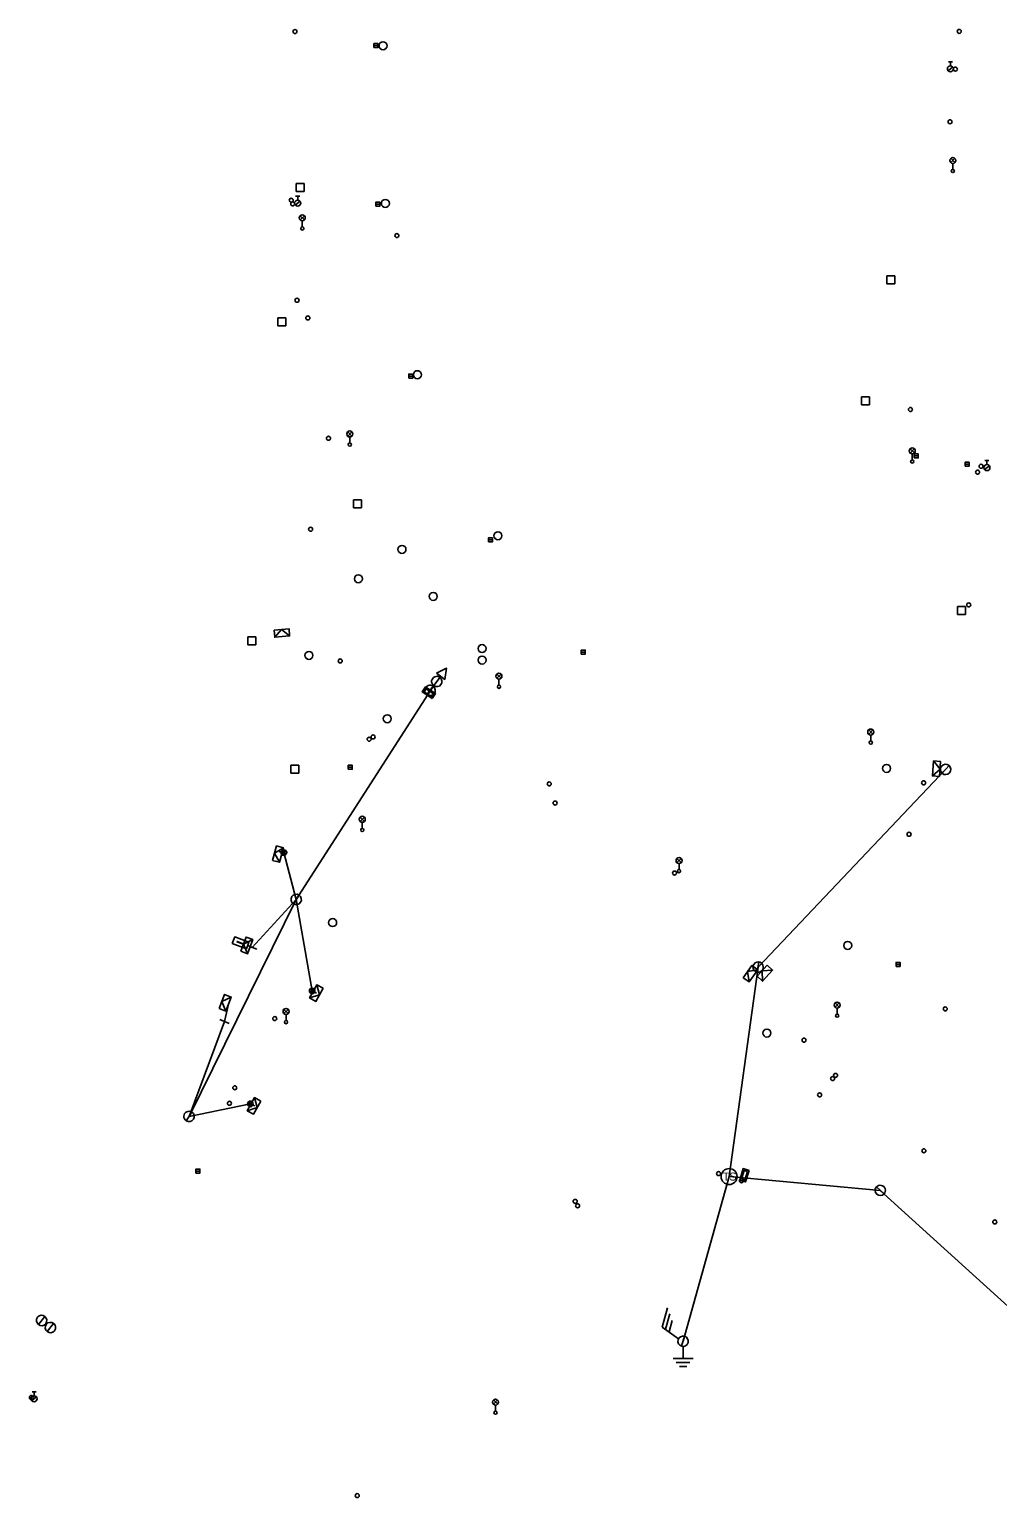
# Model space of a CAD drawing. Extents: x -544660 to -541587, y -1198996 to -1195866.
# Drawn here: x -543889.9 to -543769, y -1197450.3 to -1197266.9 of the extents above; entities that cross this region are included whole.
import ezdxf

# ---------------------------------------------------------------- set-up
doc = ezdxf.new("R2010")
doc.units = 0
doc.layers.add('CIZÍ_NADZEM', color=7, linetype='Continuous')
doc.layers.add('ELE_EON', color=7, linetype='Continuous')

msp = doc.modelspace()

# ---------------------------------------------------------------- linework, layer by layer
at = {"layer": 'CIZÍ_NADZEM'}
for p, q in [((-543846.85, -1197268.9), (-543846.35, -1197268.9)), ((-543775.11, -1197270.94), (-543774.61, -1197270.94)), ((-543774.86, -1197271.44), (-543774.86, -1197270.94)), ((-543775.15, -1197272.04), (-543774.56, -1197271.58)), ((-543774.81, -1197283.52), (-543774.29, -1197282.99)), ((-543774.28, -1197283.52), (-543774.81, -1197282.99)), ((-543774.55, -1197283.63), (-543774.55, -1197284.38)), ((-543855.55, -1197286.13), (-543856.55, -1197286.13)), ((-543856.55, -1197286.13), (-543856.55, -1197287.13)), ((-543855.55, -1197287.13), (-543855.55, -1197286.13)), ((-543856.63, -1197287.72), (-543856.13, -1197287.72)), ((-543856.55, -1197287.13), (-543855.55, -1197287.13)), ((-543856.38, -1197288.22), (-543856.38, -1197287.72)), ((-543856.67, -1197288.82), (-543856.08, -1197288.36)), ((-543846.62, -1197288.72), (-543846.12, -1197288.72)), ((-543856.06, -1197290.69), (-543855.54, -1197290.16)), ((-543855.53, -1197290.69), (-543856.06, -1197290.16)), ((-543855.8, -1197290.8), (-543855.8, -1197291.55)), ((-543781.78, -1197297.67), (-543782.78, -1197297.67)), ((-543782.78, -1197297.67), (-543782.78, -1197298.67)), ((-543782.78, -1197298.67), (-543781.78, -1197298.67)), ((-543781.78, -1197298.67), (-543781.78, -1197297.67)), ((-543857.86, -1197302.91), (-543858.86, -1197302.91)), ((-543858.86, -1197302.91), (-543858.86, -1197303.91)), ((-543858.86, -1197303.91), (-543857.86, -1197303.91)), ((-543857.86, -1197303.91), (-543857.86, -1197302.91)), ((-543842.5, -1197310.2), (-543842, -1197310.2)), ((-543784.97, -1197312.78), (-543785.97, -1197312.78)), ((-543785.97, -1197312.78), (-543785.97, -1197313.78)), ((-543784.97, -1197313.78), (-543784.97, -1197312.78)), ((-543785.97, -1197313.78), (-543784.97, -1197313.78)), ((-543850.13, -1197317.69), (-543849.61, -1197317.16)), ((-543849.6, -1197317.69), (-543850.13, -1197317.16)), ((-543849.87, -1197317.8), (-543849.87, -1197318.55)), ((-543779.88, -1197319.81), (-543779.36, -1197319.28)), ((-543779.35, -1197319.8), (-543779.88, -1197319.28)), ((-543779.62, -1197319.92), (-543779.62, -1197320.67)), ((-543779.36, -1197320.16), (-543778.86, -1197320.16)), ((-543770.54, -1197320.76), (-543770.04, -1197320.76)), ((-543770.29, -1197321.26), (-543770.29, -1197320.76)), ((-543773.03, -1197321.21), (-543772.53, -1197321.21)), ((-543770.58, -1197321.86), (-543769.99, -1197321.4)), ((-543848.39, -1197325.67), (-543849.39, -1197325.67)), ((-543849.39, -1197325.67), (-543849.39, -1197326.67)), ((-543848.39, -1197326.67), (-543848.39, -1197325.67)), ((-543849.39, -1197326.67), (-543848.39, -1197326.67)), ((-543832.56, -1197330.67), (-543832.06, -1197330.67)), ((-543772.97, -1197339), (-543773.97, -1197339)), ((-543773.97, -1197339), (-543773.97, -1197340)), ((-543772.97, -1197340), (-543772.97, -1197339)), ((-543773.97, -1197340), (-543772.97, -1197340)), ((-543861.59, -1197342.78), (-543862.59, -1197342.78)), ((-543862.59, -1197342.78), (-543862.59, -1197343.78)), ((-543861.59, -1197343.78), (-543861.59, -1197342.78)), ((-543862.59, -1197343.78), (-543861.59, -1197343.78)), ((-543820.97, -1197344.67), (-543820.47, -1197344.67)), ((-543831.5, -1197347.95), (-543830.98, -1197347.42)), ((-543830.97, -1197347.95), (-543831.5, -1197347.42)), ((-543831.24, -1197348.06), (-543831.24, -1197348.81)), ((-543785.06, -1197354.92), (-543784.54, -1197354.39)), ((-543784.53, -1197354.92), (-543785.06, -1197354.39)), ((-543784.8, -1197355.03), (-543784.8, -1197355.78)), ((-543857.22, -1197358.79), (-543857.22, -1197359.79)), ((-543856.22, -1197358.79), (-543857.22, -1197358.79)), ((-543856.22, -1197359.79), (-543856.22, -1197358.79)), ((-543850.07, -1197359.06), (-543849.57, -1197359.06)), ((-543857.22, -1197359.79), (-543856.22, -1197359.79)), ((-543848.57, -1197365.84), (-543848.05, -1197365.31)), ((-543848.04, -1197365.83), (-543848.57, -1197365.31)), ((-543848.31, -1197365.95), (-543848.31, -1197366.7)), ((-543809.01, -1197370.98), (-543808.49, -1197370.45)), ((-543808.48, -1197370.98), (-543809.01, -1197370.45)), ((-543808.75, -1197371.09), (-543808.75, -1197371.84)), ((-543781.64, -1197383.7), (-543781.14, -1197383.7)), ((-543789.26, -1197389.04), (-543788.74, -1197388.51)), ((-543788.73, -1197389.03), (-543789.26, -1197388.51)), ((-543858.09, -1197389.84), (-543857.57, -1197389.31)), ((-543857.56, -1197389.83), (-543858.09, -1197389.31)), ((-543857.83, -1197389.95), (-543857.83, -1197390.7)), ((-543789, -1197389.15), (-543789, -1197389.9)), ((-543869.08, -1197409.52), (-543868.58, -1197409.52)), ((-543889.59, -1197438.19), (-543889, -1197437.73)), ((-543889.55, -1197437.08), (-543889.05, -1197437.08)), ((-543889.3, -1197437.58), (-543889.3, -1197437.08)), ((-543831.93, -1197438.64), (-543831.41, -1197438.11)), ((-543831.4, -1197438.64), (-543831.93, -1197438.11)), ((-543831.67, -1197438.75), (-543831.67, -1197439.5))]:
    msp.add_line(p, q, dxfattribs=at)
for points in [[(-543846.85, -1197269.15), (-543846.35, -1197269.15), (-543846.35, -1197268.65), (-543846.85, -1197268.65)], [(-543846.62, -1197288.97), (-543846.12, -1197288.97), (-543846.12, -1197288.47), (-543846.62, -1197288.47)], [(-543842.5, -1197310.45), (-543842, -1197310.45), (-543842, -1197309.95), (-543842.5, -1197309.95)], [(-543779.36, -1197320.41), (-543778.86, -1197320.41), (-543778.86, -1197319.91), (-543779.36, -1197319.91)], [(-543773.03, -1197321.46), (-543772.53, -1197321.46), (-543772.53, -1197320.96), (-543773.03, -1197320.96)], [(-543832.56, -1197330.92), (-543832.06, -1197330.92), (-543832.06, -1197330.42), (-543832.56, -1197330.42)], [(-543820.97, -1197344.92), (-543820.47, -1197344.92), (-543820.47, -1197344.42), (-543820.97, -1197344.42)], [(-543850.07, -1197359.31), (-543849.57, -1197359.31), (-543849.57, -1197358.81), (-543850.07, -1197358.81)], [(-543781.64, -1197383.95), (-543781.14, -1197383.95), (-543781.14, -1197383.45), (-543781.64, -1197383.45)], [(-543869.08, -1197409.77), (-543868.58, -1197409.77), (-543868.58, -1197409.27), (-543869.08, -1197409.27)]]:
    msp.add_lwpolyline(points, close=True, dxfattribs=at)
for centre, radius in [((-543856.72, -1197267.15), 0.25), ((-543773.75, -1197267.13), 0.25), ((-543845.72, -1197268.92), 0.5), ((-543774.86, -1197271.81), 0.375), ((-543774.23, -1197271.85), 0.25), ((-543774.9, -1197278.43), 0.25), ((-543774.55, -1197283.26), 0.375), ((-543774.55, -1197284.58), 0.2), ((-543857.19, -1197288.22), 0.25), ((-543857, -1197288.68), 0.25), ((-543856.38, -1197288.59), 0.375), ((-543845.43, -1197288.63), 0.5), ((-543855.8, -1197290.43), 0.375), ((-543855.8, -1197291.75), 0.2), ((-543843.99, -1197292.64), 0.25), ((-543856.46, -1197300.73), 0.25), ((-543855.11, -1197302.93), 0.25), ((-543841.43, -1197310.02), 0.5), ((-543779.84, -1197314.37), 0.25), ((-543849.87, -1197317.43), 0.375), ((-543852.53, -1197317.97), 0.25), ((-543849.87, -1197318.75), 0.2), ((-543779.62, -1197319.54), 0.375), ((-543779.62, -1197320.87), 0.2), ((-543771.46, -1197322.2), 0.25), ((-543771.02, -1197321.46), 0.25), ((-543770.29, -1197321.63), 0.375), ((-543854.76, -1197329.33), 0.25), ((-543831.37, -1197330.14), 0.5), ((-543843.35, -1197331.85), 0.5), ((-543848.79, -1197335.52), 0.5), ((-543839.45, -1197337.72), 0.5), ((-543772.57, -1197338.78), 0.25), ((-543854.97, -1197345.09), 0.5), ((-543833.35, -1197344.23), 0.5), ((-543851.07, -1197345.78), 0.25), ((-543833.34, -1197345.68), 0.5), ((-543831.24, -1197347.69), 0.375), ((-543831.24, -1197349.01), 0.2), ((-543845.19, -1197353), 0.5), ((-543847.45, -1197355.56), 0.25), ((-543846.96, -1197355.28), 0.25), ((-543784.8, -1197354.66), 0.375), ((-543784.8, -1197355.98), 0.2), ((-543782.83, -1197359.21), 0.5), ((-543824.96, -1197361.14), 0.25), ((-543778.2, -1197361.01), 0.25), ((-543824.22, -1197363.53), 0.25), ((-543848.31, -1197365.57), 0.375), ((-543848.31, -1197366.9), 0.2), ((-543780.02, -1197367.44), 0.25), ((-543808.75, -1197370.72), 0.375), ((-543809.31, -1197372.28), 0.25), ((-543808.75, -1197372.04), 0.2), ((-543852.01, -1197378.47), 0.5), ((-543787.68, -1197381.33), 0.5), ((-543789, -1197388.78), 0.375), ((-543859.24, -1197390.46), 0.25), ((-543857.83, -1197389.57), 0.375), ((-543789, -1197390.1), 0.2), ((-543775.5, -1197389.25), 0.25), ((-543857.83, -1197390.9), 0.2), ((-543797.78, -1197392.27), 0.5), ((-543793.13, -1197393.16), 0.25), ((-543789.56, -1197397.95), 0.25), ((-543789.2, -1197397.56), 0.25), ((-543864.23, -1197399.11), 0.25), ((-543791.19, -1197399.99), 0.25), ((-543864.9, -1197401.04), 0.25), ((-543778.17, -1197406.98), 0.25), ((-543803.81, -1197409.83), 0.25), ((-543800.95, -1197410.72), 0.25), ((-543821.72, -1197413.3), 0.25), ((-543821.41, -1197413.85), 0.25), ((-543769.31, -1197415.87), 0.25), ((-543889.64, -1197437.79), 0.25), ((-543889.3, -1197437.96), 0.375), ((-543831.67, -1197438.38), 0.375), ((-543831.67, -1197439.7), 0.2), ((-543848.94, -1197450.06), 0.25)]:
    msp.add_circle(centre, radius, dxfattribs=at)
at = {"layer": 'ELE_EON'}
for p, q in [((-543838.6, -1197347.83), (-543839.39, -1197348.87)), ((-543839.45, -1197348.95), (-543840.24, -1197349.99)), ((-543775.02, -1197358.86), (-543775.9, -1197359.82)), ((-543858.44, -1197369.66), (-543858.69, -1197369.6)), ((-543856.21, -1197375.03), (-543856.91, -1197376.13)), ((-543862.66, -1197381.35), (-543861.48, -1197381.79)), ((-543798.77, -1197383.39), (-543798.97, -1197384.67)), ((-543854.26, -1197387.18), (-543854.04, -1197387.3)), ((-543866.09, -1197390.57), (-543864.95, -1197391.07)), ((-543861.97, -1197401.27), (-543861.75, -1197401.38)), ((-543869.59, -1197402.15), (-543870.31, -1197403.23)), ((-543783.14, -1197412.37), (-543784.1, -1197411.49)), ((-543810.86, -1197429), (-543810.19, -1197426.59)), ((-543810.42, -1197429.28), (-543809.88, -1197427.35)), ((-543887.95, -1197427.67), (-543888.76, -1197428.69)), ((-543886.86, -1197428.55), (-543887.67, -1197429.57)), ((-543808.83, -1197430.46), (-543810.86, -1197429)), ((-543809.99, -1197429.61), (-543809.59, -1197428.16)), ((-543808.06, -1197430.14), (-543808.42, -1197431.4)), ((-543808.24, -1197432.92), (-543808.24, -1197431.42)), ((-543809.49, -1197432.92), (-543806.99, -1197432.92)), ((-543809.09, -1197433.42), (-543807.39, -1197433.42)), ((-543808.69, -1197433.92), (-543807.79, -1197433.92))]:
    msp.add_line(p, q, dxfattribs=at)
for points in [[(-543859.32, -1197341.92), (-543857.45, -1197341.76), (-543857.38, -1197342.66), (-543859.24, -1197342.82)], [(-543839.05, -1197347.32), (-543837.78, -1197346.7), (-543838.01, -1197348.09)], [(-543839.58, -1197350.49), (-543840.82, -1197349.65), (-543840.4, -1197349.03), (-543839.16, -1197349.87)], [(-543839.66, -1197350.25), (-543840.57, -1197349.64), (-543840.32, -1197349.27), (-543839.41, -1197349.88)], [(-543776.22, -1197360.22), (-543776.07, -1197358.35), (-543776.96, -1197358.28), (-543777.11, -1197360.15)], [(-543859.53, -1197370.7), (-543859.02, -1197368.89), (-543858.16, -1197369.14), (-543858.66, -1197370.94)], [(-543864.55, -1197381.1), (-543862.79, -1197381.76), (-543862.48, -1197380.92), (-543864.23, -1197380.26)], [(-543863.96, -1197380.86), (-543863.08, -1197381.19), (-543863.07, -1197381.16), (-543863.94, -1197380.83)], [(-543863.48, -1197382.04), (-543862.82, -1197380.28), (-543861.98, -1197380.6), (-543862.64, -1197382.36)], [(-543800.74, -1197385.36), (-543799.65, -1197383.83), (-543798.92, -1197384.36), (-543800, -1197385.88)], [(-543797.73, -1197383.8), (-543799, -1197385.18), (-543798.34, -1197385.79), (-543797.07, -1197384.41)], [(-543853.21, -1197386.68), (-543854.11, -1197388.32), (-543854.9, -1197387.89), (-543854, -1197386.25)], [(-543866.19, -1197389.19), (-543865.5, -1197387.45), (-543864.67, -1197387.78), (-543865.35, -1197389.52)], [(-543860.97, -1197400.78), (-543861.9, -1197402.41), (-543862.68, -1197401.97), (-543861.76, -1197400.33)], [(-543800, -1197409.44), (-543800.45, -1197410.87), (-543801.16, -1197410.65), (-543800.72, -1197409.21)], [(-543800.2, -1197409.58), (-543800.53, -1197410.63), (-543800.96, -1197410.5), (-543800.63, -1197409.45)]]:
    msp.add_lwpolyline(points, close=True, dxfattribs=at)
for points in [[(-543859.24, -1197342.82), (-543858.39, -1197341.84), (-543857.38, -1197342.66)], [(-543839.42, -1197348.91), (-543856.56, -1197375.58), (-543869.95, -1197402.69)], [(-543802.49, -1197410.2), (-543798.87, -1197384.03), (-543775.46, -1197359.34)], [(-543777.11, -1197360.15), (-543776.14, -1197359.29), (-543776.96, -1197358.28)], [(-543858.66, -1197370.94), (-543859.28, -1197369.8), (-543858.16, -1197369.14)], [(-543856.56, -1197375.58), (-543858.1, -1197369.73), (-543858.41, -1197370.04)], [(-543856.56, -1197375.58), (-543862.07, -1197381.57), (-543862.31, -1197381.48)], [(-543856.56, -1197375.58), (-543854.57, -1197387.01), (-543854.45, -1197387.07)], [(-543862.64, -1197382.36), (-543863.15, -1197381.16), (-543861.98, -1197380.6)], [(-543800, -1197385.88), (-543800.19, -1197384.6), (-543798.92, -1197384.36)], [(-543797.07, -1197384.41), (-543798.37, -1197384.49), (-543798.34, -1197385.79)], [(-543854, -1197386.25), (-543853.66, -1197387.5), (-543854.9, -1197387.89)], [(-543869.95, -1197402.69), (-543865.52, -1197390.82), (-543865.01, -1197388.65)], [(-543865.35, -1197389.52), (-543865.85, -1197388.32), (-543864.67, -1197387.78)], [(-543869.95, -1197402.69), (-543862.29, -1197401.12), (-543862.22, -1197401.15)], [(-543861.76, -1197400.33), (-543861.44, -1197401.59), (-543862.68, -1197401.97)], [(-543808.24, -1197430.77), (-543802.49, -1197410.2)], [(-543802.49, -1197410.2), (-543783.62, -1197411.93), (-543767.65, -1197426.45)]]:
    msp.add_lwpolyline(points, dxfattribs=at)
for centre, radius in [((-543858.1, -1197369.73), 0.35), ((-543858.1, -1197369.73), 0.175), ((-543854.57, -1197387.01), 0.35), ((-543854.57, -1197387.01), 0.175), ((-543862.29, -1197401.12), 0.35), ((-543862.29, -1197401.12), 0.175), ((-543802.49, -1197410.2), 1)]:
    msp.add_circle(centre, radius, dxfattribs=at)
for centre, start, end in [((-543839, -1197348.35), 52.78, 232.78), ((-543839, -1197348.35), 232.78, 52.78), ((-543839.84, -1197349.47), 52.78, 232.78), ((-543839.84, -1197349.47), 232.78, 52.78), ((-543775.46, -1197359.34), 47.41, 227.41), ((-543775.46, -1197359.34), 227.41, 47.41), ((-543856.56, -1197375.58), 57.27, 237.27), ((-543856.56, -1197375.58), 237.27, 57.27), ((-543798.87, -1197384.03), 81.46, 261.46), ((-543798.87, -1197384.03), 261.46, 81.46), ((-543869.95, -1197402.69), 56.88, 236.88), ((-543869.95, -1197402.69), 236.88, 56.88), ((-543783.62, -1197411.93), 137.59, 317.59), ((-543783.62, -1197411.93), 317.59, 137.59), ((-543888.36, -1197428.18), 51.24, 231.24), ((-543888.36, -1197428.18), 231.24, 51.24), ((-543887.26, -1197429.06), 51.24, 231.24), ((-543887.26, -1197429.06), 231.24, 51.24), ((-543808.24, -1197430.77), 74.38, 254.38), ((-543808.24, -1197430.77), 254.38, 74.38)]:
    msp.add_arc(centre, 0.65, start, end, dxfattribs=at)

# ---------------------------------------------------------------- texts
msp.add_text('TS', height=1, dxfattribs=at).set_placement((-543803.28, -1197410.7))

doc.saveas('drawing.dxf')
